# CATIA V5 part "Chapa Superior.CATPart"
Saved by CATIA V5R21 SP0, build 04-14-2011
Part number: Chapa Superior
Definition: Chapa Superior
Nomenclature: Chapa Superior
Source: Unknown
Bounding box of the stored display mesh (mm): x -6 to 6, y -4.6 to 1.5, z -5 to 5
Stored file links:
  C:\Users\beatr\OneDrive\Documents\UNB\2026_1\Pi1\Componentes eletronicos\Chapa Superior.CATPart
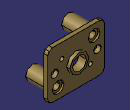
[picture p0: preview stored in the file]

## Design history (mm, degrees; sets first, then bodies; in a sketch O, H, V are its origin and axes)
Body1 "Sólido1" (main body)
  Solid1: solid without history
